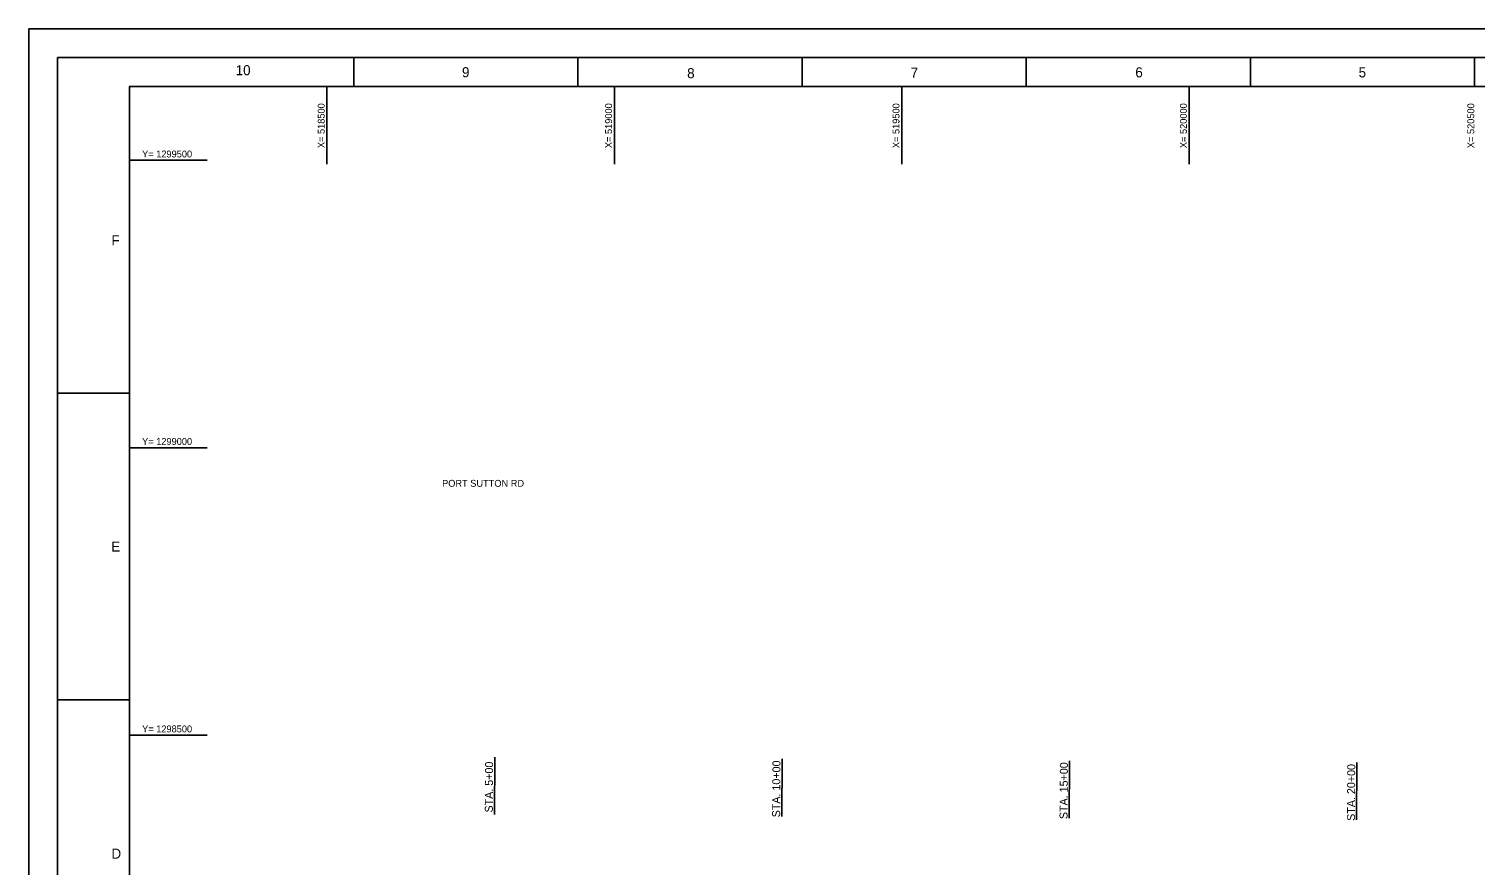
# Model space of a CAD drawing. Extents: x 517982 to 522382, y 1296329 to 1299729.
# Drawn here: x 517982 to 520497, y 1298274 to 1299729 of the extents above; entities that cross this region are included whole.
import ezdxf

# ---------------------------------------------------------------- set-up
doc = ezdxf.new("R2010")
doc.units = 0
for name, color, linetype in [('G-ANNO-NPLT', 7, 'Continuous'), ('G-ANNO-TTLB', 7, 'Continuous'), ('V-ALGN-TEXT', 7, 'Continuous'), ('V-ROAD-IDEN', 7, 'Continuous'), ('V-TOPO-COOR-STAT', 7, 'Continuous')]:
    doc.layers.add(name, color=color, linetype=linetype)

msp = doc.modelspace()

# ---------------------------------------------------------------- linework, layer by layer
at = {"layer": 'G-ANNO-NPLT'}
msp.add_lwpolyline([(517981.5, 1299728.6), (522381.5, 1299728.6), (522381.5, 1296328.6), (517981.5, 1296328.6)], close=True, dxfattribs=at)
msp.add_lwpolyline([(517981.5, 1299678.6), (517981.5, 1299728.6), (518031.5, 1299728.6)], dxfattribs=at)
at = {"layer": 'G-ANNO-TTLB'}
for p, q in [((518546.5, 1299678.6), (518546.5, 1299628.6)), ((518936.5, 1299678.6), (518936.5, 1299628.6)), ((518936.5, 1299678.6), (518936.5, 1299628.6)), ((519326.5, 1299678.6), (519326.5, 1299628.6)), ((519716.5, 1299678.6), (519716.5, 1299628.6)), ((520106.5, 1299678.6), (520106.5, 1299628.6)), ((520496.5, 1299678.6), (520496.5, 1299628.6)), ((518031.5, 1299095.1), (518156.5, 1299095.1)), ((518031.5, 1298561.8), (518156.5, 1298561.8))]:
    msp.add_line(p, q, dxfattribs=at)
for points in [[(518031.5, 1296378.6), (522331.5, 1296378.6), (522331.5, 1299678.6), (518031.5, 1299678.6)], [(522281.5, 1299628.6), (518156.5, 1299628.6), (518156.5, 1296428.6), (522281.5, 1296428.6)]]:
    msp.add_lwpolyline(points, close=True, dxfattribs=at)
at = {"layer": 'V-ALGN-TEXT'}
for p, q in [((518791.2, 1298361.9), (518791.8, 1298461.9)), ((519291.2, 1298358.8), (519291.8, 1298458.8)), ((519791.2, 1298355.8), (519791.8, 1298455.8)), ((520291.2, 1298352.7), (520291.8, 1298452.7))]:
    msp.add_line(p, q, dxfattribs=at)
at = {"layer": 'V-TOPO-COOR-STAT'}
for p, q in [((518500, 1299493.6), (518500, 1299628.6)), ((519000, 1299493.6), (519000, 1299628.6)), ((519500, 1299493.6), (519500, 1299628.6)), ((520000, 1299493.6), (520000, 1299628.6)), ((518291.5, 1299500), (518156.5, 1299500)), ((518291.5, 1299000), (518156.5, 1299000)), ((518291.5, 1298500), (518156.5, 1298500))]:
    msp.add_line(p, q, dxfattribs=at)

# ---------------------------------------------------------------- texts
at = {"layer": 'G-ANNO-TTLB'}
for s, p in [('10', (518341.1, 1299648)), ('9', (518734.9, 1299644.5)), ('8', (519126.6, 1299642.8)), ('7', (519515.4, 1299643.6)), ('6', (519906.3, 1299644.3)), ('5', (520294.8, 1299644.2)), ('F', (518125.1, 1299352.2)), ('E', (518124.9, 1298819.5)), ('D', (518125.1, 1298285.3))]:
    msp.add_text(s, height=17.5, dxfattribs=at).set_placement(p)
at = {"layer": 'V-ALGN-TEXT'}
for s, p in [('STA. 5+00', (518788.5, 1298365.6)), ('STA. 10+00', (519288.4, 1298357.2)), ('STA. 15+00', (519788.4, 1298354.1)), ('STA. 20+00', (520288.4, 1298351.1))]:
    msp.add_text(s, height=13.92, rotation=89.6504, dxfattribs=at).set_placement(p)
at = {"layer": 'V-ROAD-IDEN'}
msp.add_text('PORT SUTTON RD', height=12, dxfattribs=at).set_placement((518700.3, 1298932.2))
at = {"layer": 'V-TOPO-COOR-STAT'}
for s, p in [('X= 518500', (518496, 1299521.2)), ('X= 519000', (518996, 1299521.2)), ('X= 519500', (519496, 1299521.2)), ('X= 520000', (519996, 1299521.2)), ('X= 520500', (520496, 1299521.2))]:
    msp.add_text(s, height=12, rotation=90, dxfattribs=at).set_placement(p)
for s, p in [('Y= 1299500', (518178.4, 1299505)), ('Y= 1299000', (518178.4, 1299005)), ('Y= 1298500', (518178.4, 1298505))]:
    msp.add_text(s, height=12, dxfattribs=at).set_placement(p)

doc.saveas('drawing.dxf')
